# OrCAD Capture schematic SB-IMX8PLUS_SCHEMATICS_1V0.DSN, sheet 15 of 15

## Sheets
15 15. Mechanical: size B; title: SB-iMX8PLUS      15. Mechanical
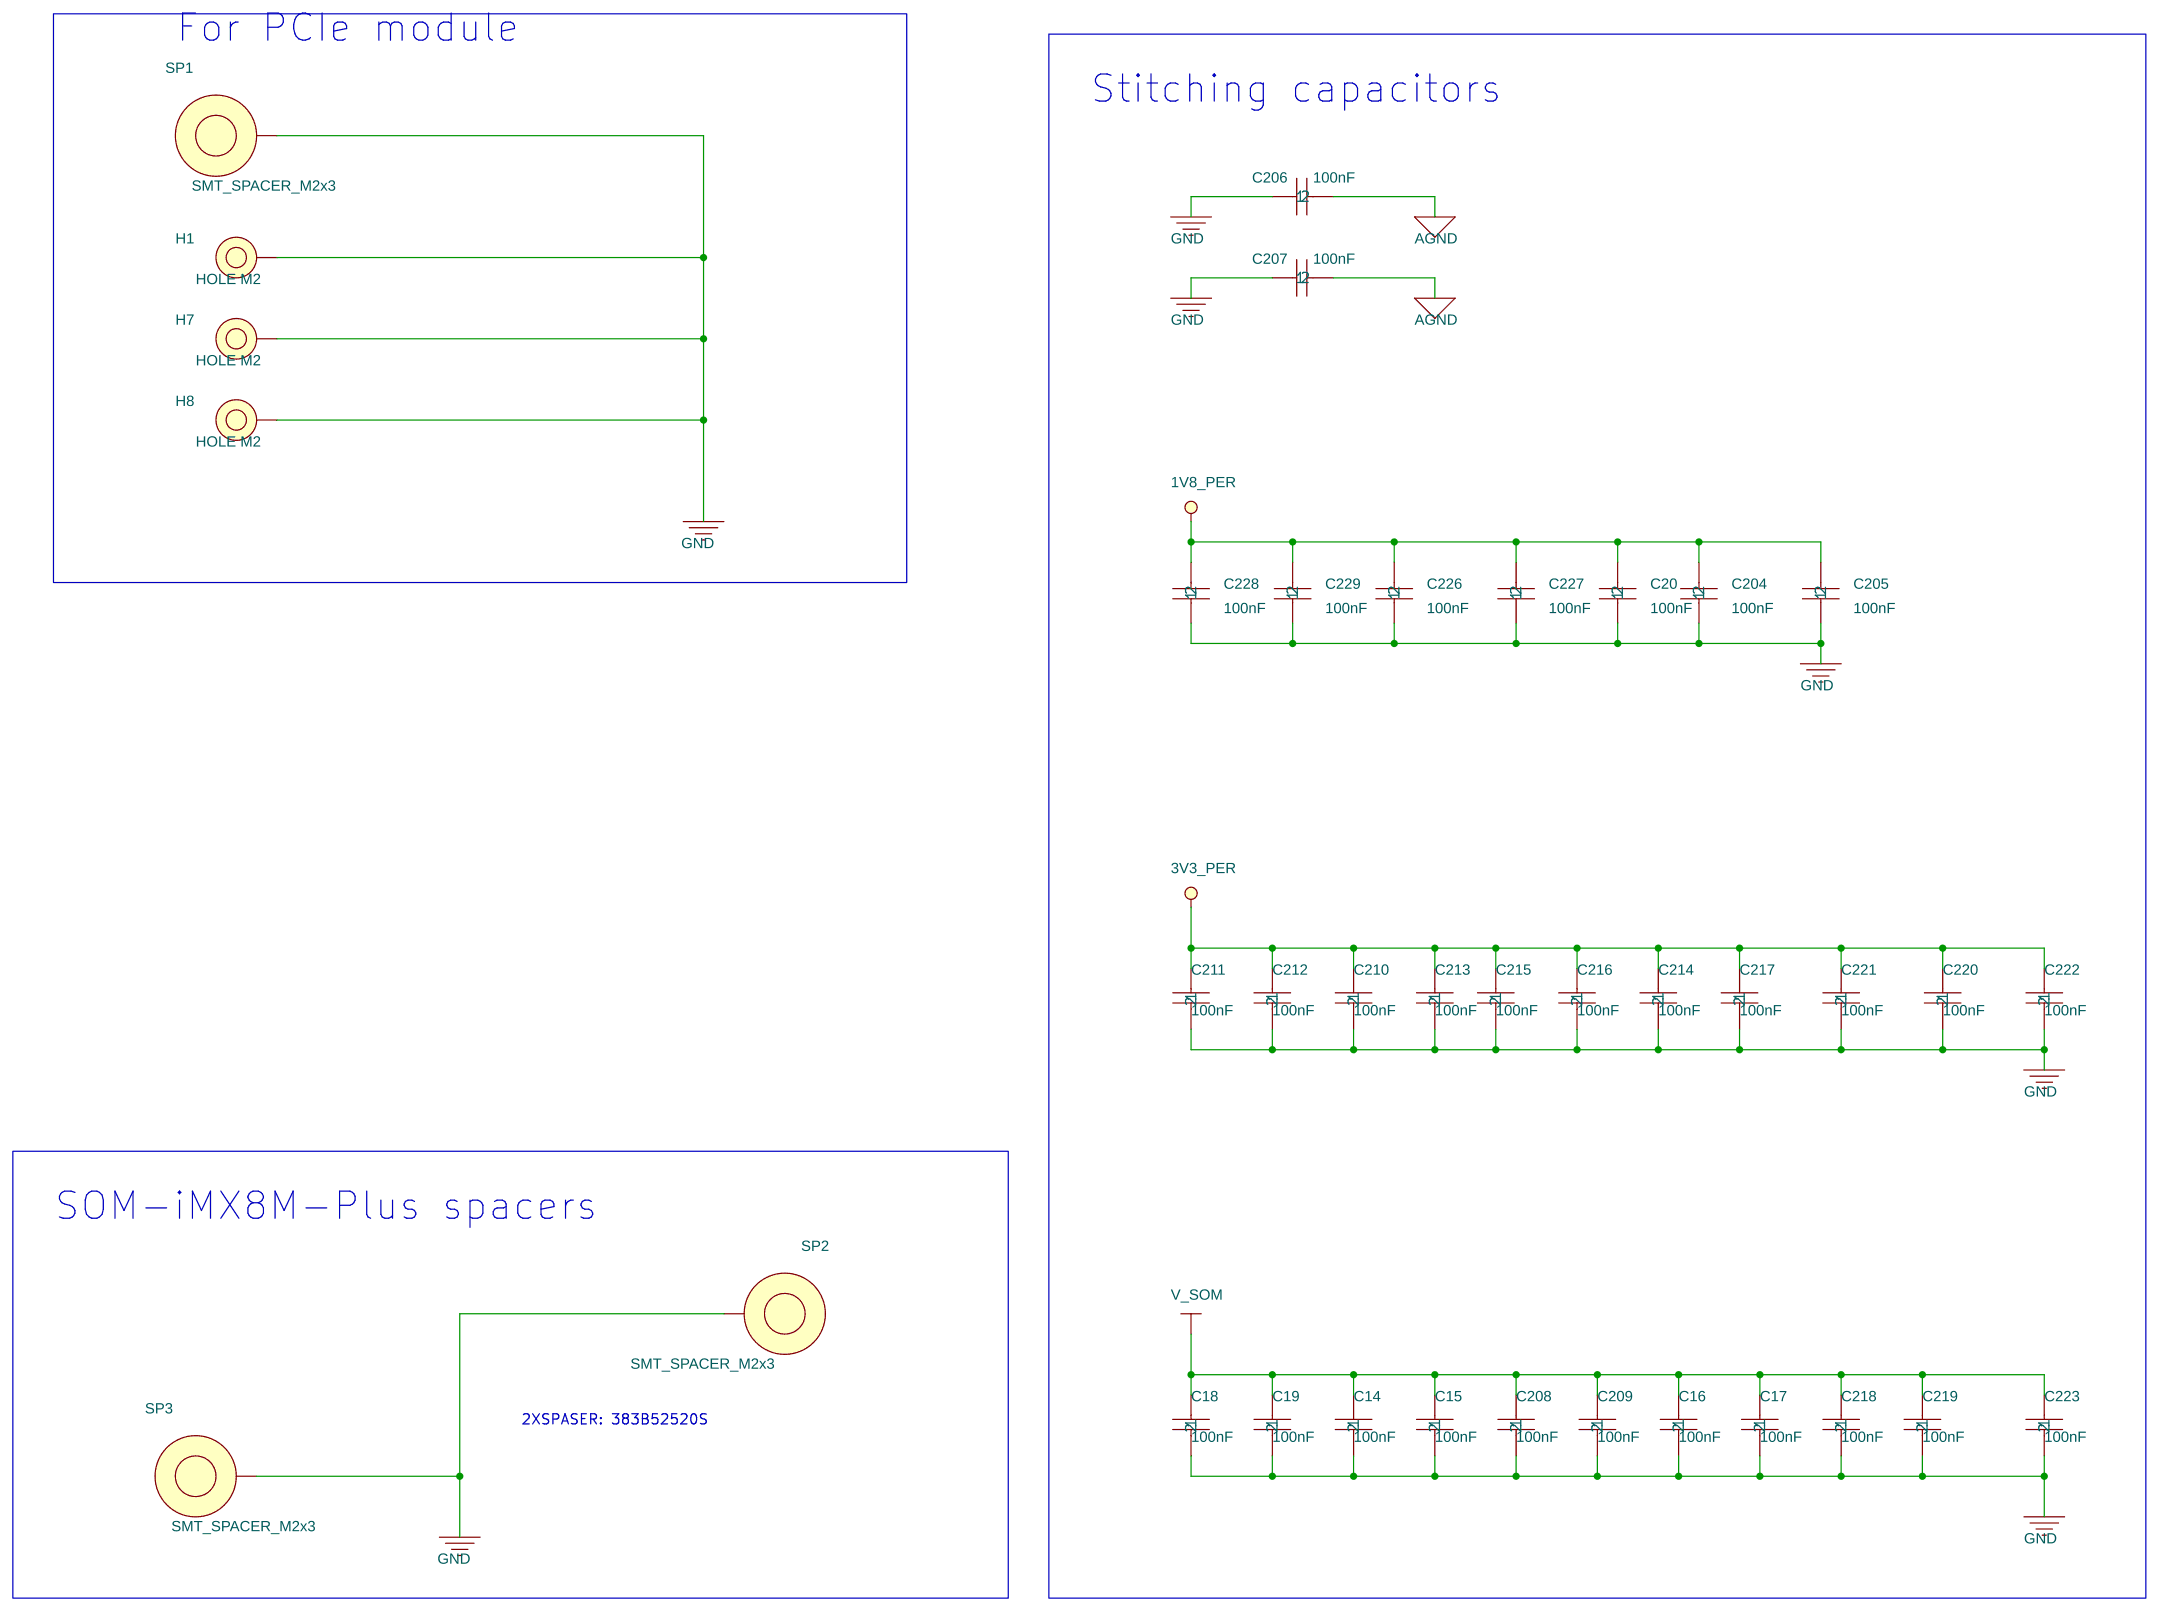
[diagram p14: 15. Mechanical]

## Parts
C14  100nF  [RC0402]
C15  100nF  [RC0402]
C16  100nF  [RC0402]
C17  100nF  [RC0402]
C18  100nF  [RC0402]
C19  100nF  [RC0402]
C20  100nF  [RC0402]
C204  100nF  [RC0402]
C205  100nF  [RC0402]
C206  100nF  [RC0402]
C207  100nF  [RC0402]
C208  100nF  [RC0402]
C209  100nF  [RC0402]
C210  100nF  [RC0402]
C211  100nF  [RC0402]
C212  100nF  [RC0402]
C213  100nF  [RC0402]
C214  100nF  [RC0402]
C215  100nF  [RC0402]
C216  100nF  [RC0402]
C217  100nF  [RC0402]
C218  100nF  [RC0402]
C219  100nF  [RC0402]
C220  100nF  [RC0402]
C221  100nF  [RC0402]
C222  100nF  [RC0402]
C223  100nF  [RC0402]
C226  100nF  [RC0402]
C227  100nF  [RC0402]
C228  100nF  [RC0402]
C229  100nF  [RC0402]
H1  HOLE M2  [M2PAD]
H7  HOLE M2  [M2PAD]
H8  HOLE M2  [M2PAD]
SP1  SMT_SPACER_M2x3  [MINIPCIE-4-Spacer]
SP2  SMT_SPACER_M2x3  [MINIPCIE-4-Spacer]
SP3  SMT_SPACER_M2x3  [MINIPCIE-4-Spacer]

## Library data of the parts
C14 = 100nF,_10V,_X7R,_10%,_0402_19: CLABCONF0: = SB-iMX8PLUS; P/N: 151B10400S
C15 = 100nF,_10V,_X7R,_10%,_0402_26: CLABCONF0: = SB-iMX8PLUS; P/N: 151B10400S
C16 = 100nF,_10V,_X7R,_10%,_0402_11: CLABCONF0: = SB-iMX8PLUS; P/N: 151B10400S
C17 = 100nF,_10V,_X7R,_10%,_0402_21: CLABCONF0: = SB-iMX8PLUS; P/N: 151B10400S
C18 = 100nF,_10V,_X7R,_10%,_0402_24: CLABCONF0: = SB-iMX8PLUS; P/N: 151B10400S
C19 = 100nF,_10V,_X7R,_10%,_0402_27: CLABCONF0: = SB-iMX8PLUS; P/N: 151B10400S
C20 = 100nF,_10V,_X7R,_10%,_0402_18: CLABCONF0: = SB-iMX8PLUS; P/N: 151B10400S
C204 = 100nF,_10V,_X7R,_10%,_0402_2: CLABCONF0: = SB-iMX8PLUS; P/N: 151B10400S
C205 = 100nF,_10V,_X7R,_10%,_0402_23: CLABCONF0: = SB-iMX8PLUS; P/N: 151B10400S
C206 = 100nF,_10V,_X7R,_10%,_0402_25: CLABCONF0: = SB-iMX8PLUS; P/N: 151B10400S
C207 = 100nF,_10V,_X7R,_10%,_0402_10: CLABCONF0: = SB-iMX8PLUS; P/N: 151B10400S
C208 = 100nF,_10V,_X7R,_10%,_0402_14: CLABCONF0: = SB-iMX8PLUS; P/N: 151B10400S
C209 = 100nF,_10V,_X7R,_10%,_0402_16: CLABCONF0: = SB-iMX8PLUS; P/N: 151B10400S
C210 = 100nF,_10V,_X7R,_10%,_0402: CLABCONF0: = SB-iMX8PLUS; P/N: 151B10400S
C211 = 100nF,_10V,_X7R,_10%,_0402_3: CLABCONF0: = SB-iMX8PLUS; P/N: 151B10400S
C212 = 100nF,_10V,_X7R,_10%,_0402_6: CLABCONF0: = SB-iMX8PLUS; P/N: 151B10400S
C213 = 100nF,_10V,_X7R,_10%,_0402_9: CLABCONF0: = SB-iMX8PLUS; P/N: 151B10400S
C214 = 100nF,_10V,_X7R,_10%,_0402_13: CLABCONF0: = SB-iMX8PLUS; P/N: 151B10400S
C215 = 100nF,_10V,_X7R,_10%,_0402_15: CLABCONF0: = SB-iMX8PLUS; P/N: 151B10400S
C216 = 100nF,_10V,_X7R,_10%,_0402_20: CLABCONF0: = SB-iMX8PLUS; P/N: 151B10400S
C217 = 100nF,_10V,_X7R,_10%,_0402_22: CLABCONF0: = SB-iMX8PLUS; P/N: 151B10400S
C218 = 100nF,_10V,_X7R,_10%,_0402_29: CLABCONF0: = SB-iMX8PLUS; P/N: 151B10400S
C219 = 100nF,_10V,_X7R,_10%,_0402_5: CLABCONF0: = SB-iMX8PLUS; P/N: 151B10400S
C220 = 100nF,_10V,_X7R,_10%,_0402_4: CLABCONF0: = SB-iMX8PLUS; P/N: 151B10400S
C221 = 100nF,_10V,_X7R,_10%,_0402_7: CLABCONF0: = SB-iMX8PLUS; P/N: 151B10400S
C222 = 100nF,_10V,_X7R,_10%,_0402_28: CLABCONF0: = SB-iMX8PLUS; P/N: 151B10400S
C223 = 100nF,_10V,_X7R,_10%,_0402_17: CLABCONF0: = SB-iMX8PLUS; P/N: 151B10400S
C226 = 100nF,_10V,_X7R,_10%,_0402_30: CLABCONF0: = SB-iMX8PLUS; P/N: 151B10400S
C227 = 100nF,_10V,_X7R,_10%,_0402_1: CLABCONF0: = SB-iMX8PLUS; P/N: 151B10400S
C228 = 100nF,_10V,_X7R,_10%,_0402_8: CLABCONF0: = SB-iMX8PLUS; P/N: 151B10400S
C229 = 100nF,_10V,_X7R,_10%,_0402_12: CLABCONF0: = SB-iMX8PLUS; P/N: 151B10400S
H1 H7 H8 = Hole,_Plated,_M2,_5mm._ext.: CLABCONF0: DNP
SP1-SP3 = SMT_SPACER_M2x3_1: CLABCONF0: = SB-iMX8PLUS

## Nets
1V8_PER: C20.2 C204.2 C205.2 C226.2 C227.2 C228.2 C229.2 ; also on sheet 6 10 11 13
3V3_PER: C210.1 C211.1 C212.1 C213.1 C214.1 C215.1 C216.1 C217.1 C220.1 C221.1 C222.1 ; also on sheet 2 4 5 6 7 8 9 10 11 12 13 14
AGND: C206.2 C207.2 ; also on sheet 5
GND: C14.2 C15.2 C16.2 C17.2 C18.2 C19.2 C20.1 C204.1 C205.1 C206.1 C207.1 C208.2 C209.2 C210.2 C211.2 C212.2 C213.2 C214.2 C215.2 C216.2 C217.2 C218.2 C219.2 C220.2 C221.2 C222.2 C223.2 C226.1 C227.1 C228.1 C229.1 H1.1 H7.1 H8.1 SP1.NC(1) SP2.NC(1) SP3.NC(1) ; also on sheet 2 3 4 5 6 7 8 9 10 11 12 13 14
V_SOM: C14.1 C15.1 C16.1 C17.1 C18.1 C19.1 C208.1 C209.1 C218.1 C219.1 C223.1 ; also on sheet 2 13

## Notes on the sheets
sheet 15
- For PCIe module
- Stitching capacitors
- SOM-iMX8M-Plus spacers
- 2XSPASER: 383B52520S
